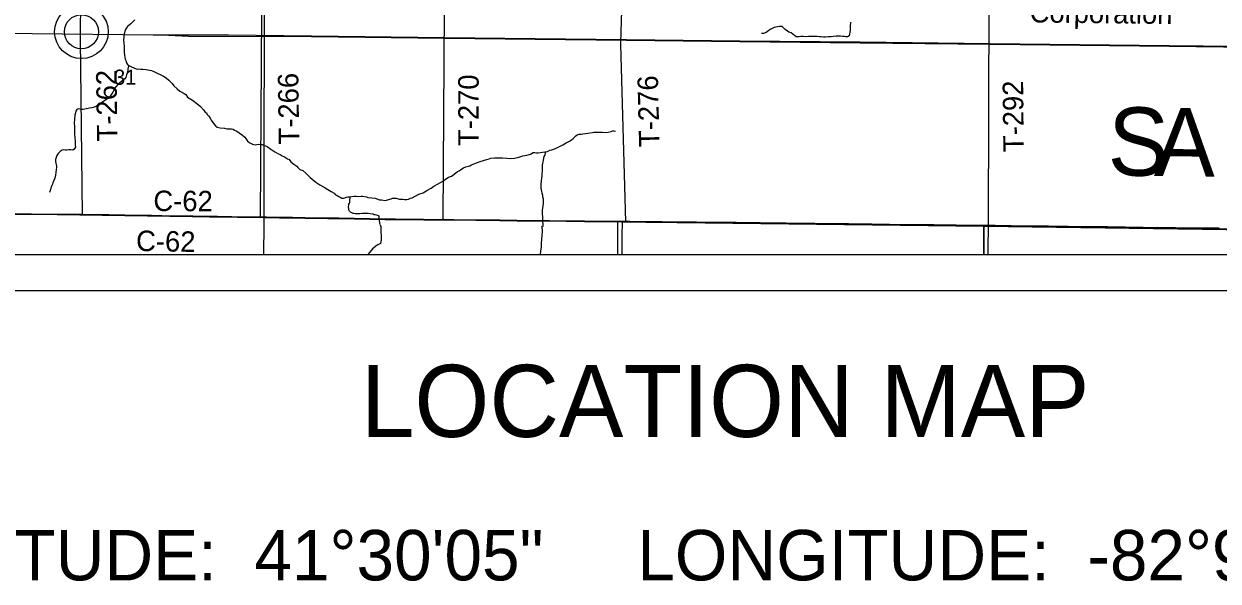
# Model space of a CAD drawing. Extents: x 0 to 34, y 0 to 22.
# Drawn here: x 3.493 to 6.805, y 13.194 to 14.74 of the extents above; entities that cross this region are included whole.
import ezdxf

# ---------------------------------------------------------------- set-up
doc = ezdxf.new("R2010")
doc.units = 0
for name, color, linetype in [('GM_X_County_Road', 7, 'Continuous'), ('GM_X_County_Road_Text', 7, 'Continuous'), ('GM_X_County_Text', 7, 'Continuous'), ('GM_X_Minor_River', 7, 'Continuous'), ('GM_X_Rail_Line', 7, 'Continuous'), ('GM_X_Rail_Line_Text', 7, 'Continuous'), ('GM_X_Section', 7, 'Continuous'), ('GM_X_Section_Text', 7, 'Continuous'), ('GM_X_Township_Road', 7, 'Continuous'), ('GM_X_Township_Road_Text', 7, 'Continuous'), ('GM_X_Unincorporated', 7, 'Continuous'), ('GM_X_Unincorporated_Location', 7, 'Continuous'), ('SH_Cut_Line', 7, 'Continuous'), ('SH_Data', 7, 'Continuous'), ('SH_Text', 7, 'Continuous')]:
    doc.layers.add(name, color=color, linetype=linetype)

msp = doc.modelspace()

# ---------------------------------------------------------------- linework, layer by layer
at = {"layer": 'GM_X_County_Road'}
msp.add_line((5.1526, 14.1908), (5.1623, 14.1907), dxfattribs=at)
for points in [[(3.1493, 14.2166), (3.1515, 14.2166), (3.2852, 14.2149), (3.3044, 14.2146), (3.3778, 14.2136), (3.4331, 14.2126), (3.4692, 14.2121), (3.5139, 14.2114), (3.586, 14.2106), (3.6556, 14.21)], [(3.6556, 14.21), (3.6718, 14.2099), (3.7284, 14.2091), (3.7731, 14.2086), (3.8465, 14.2072), (3.9043, 14.2062), (3.944, 14.206), (3.9621, 14.2057), (4.0074, 14.2048), (4.0298, 14.2045), (4.0696, 14.2041), (4.1317, 14.2031), (4.1559, 14.2029), (4.1594, 14.2029)], [(4.1594, 14.2029), (4.1659, 14.2028), (4.2013, 14.202), (4.2374, 14.2016), (4.2722, 14.2011), (4.3101, 14.2005), (4.3356, 14.2002), (4.3667, 14.1998), (4.4947, 14.1973), (4.5233, 14.1971), (4.5599, 14.1967), (4.6015, 14.1964), (4.6438, 14.1959), (4.655, 14.1959)], [(4.655, 14.1959), (4.6854, 14.1957), (4.7463, 14.1947), (4.8128, 14.1943), (4.86, 14.1937), (4.9502, 14.1929), (4.9968, 14.1921), (5.0478, 14.1916), (5.1273, 14.191), (5.1526, 14.1908)], [(5.1623, 14.1907), (5.1733, 14.1906), (5.2175, 14.19), (5.2629, 14.1896), (5.3169, 14.189), (5.3586, 14.1886), (5.4139, 14.1884), (5.468, 14.1877), (5.5351, 14.187), (5.5798, 14.1865), (5.6066, 14.1863), (5.6861, 14.1852), (5.7794, 14.1841), (5.8446, 14.1835), (5.8938, 14.1827), (5.9329, 14.182), (5.9596, 14.1818), (5.9895, 14.1814), (6.0162, 14.1812), (6.0435, 14.1807), (6.0784, 14.1803), (6.1169, 14.1801), (6.1474, 14.1798), (6.1678, 14.1796)], [(6.1678, 14.1796), (6.1865, 14.1794), (6.2754, 14.1783), (6.3065, 14.1782), (6.3345, 14.1776), (6.4439, 14.1764), (6.4992, 14.1756), (6.5968, 14.1744), (6.6366, 14.1738), (6.6608, 14.1736), (6.6869, 14.1732), (6.718, 14.1728), (6.8082, 14.1723), (6.8964, 14.1713), (6.9586, 14.1708), (7.0189, 14.1698), (7.1414, 14.1682), (7.177, 14.168)]]:
    msp.add_lwpolyline(points, dxfattribs=at)
at = {"layer": 'GM_X_Minor_River'}
for points in [[(3.8008, 14.7511), (3.7894, 14.7396), (3.7849, 14.7365), (3.7804, 14.7327), (3.7773, 14.7285), (3.7743, 14.7236), (3.7725, 14.719), (3.7717, 14.7144), (3.7702, 14.708), (3.7695, 14.7027), (3.7692, 14.6947), (3.7696, 14.6859), (3.7704, 14.6765), (3.7708, 14.6727), (3.7709, 14.6609), (3.7713, 14.6529), (3.7724, 14.6472), (3.774, 14.6419), (3.7755, 14.6377), (3.7775, 14.6317), (3.7801, 14.6271), (3.7855, 14.623), (3.7893, 14.6215), (3.7992, 14.6166), (3.8064, 14.6143), (3.8113, 14.6147), (3.8166, 14.614), (3.8223, 14.6144), (3.8318, 14.6129), (3.841, 14.6111), (3.8466, 14.6107), (3.8527, 14.6073), (3.8626, 14.6028), (3.8725, 14.5979), (3.8798, 14.5945), (3.8877, 14.5896), (3.895, 14.5836), (3.8996, 14.5791), (3.9038, 14.5745), (3.9087, 14.5681), (3.9175, 14.5594), (3.9255, 14.5534), (3.9373, 14.5466), (3.9419, 14.5436), (3.9465, 14.5364), (3.951, 14.5333), (3.9606, 14.5277), (3.9724, 14.5186), (3.9827, 14.5107), (3.9911, 14.5012), (3.9941, 14.4952), (3.9987, 14.4925), (4.001, 14.4884), (4.0048, 14.4846), (4.0071, 14.4808), (4.0098, 14.4766), (4.0125, 14.4729), (4.0163, 14.466), (4.0243, 14.457), (4.0289, 14.4532), (4.0372, 14.4513), (4.0486, 14.4499), (4.0555, 14.4484), (4.0638, 14.4488), (4.0684, 14.4484), (4.0726, 14.4477), (4.0767, 14.4451), (4.0832, 14.442), (4.0893, 14.4375), (4.0992, 14.4311), (4.1057, 14.4258), (4.1084, 14.4213), (4.1111, 14.4175), (4.1141, 14.4137), (4.1191, 14.4095), (4.1229, 14.4077), (4.1267, 14.4062), (4.1339, 14.4043), (4.143, 14.4062), (4.1487, 14.4051), (4.1532, 14.4048), (4.1593, 14.4025), (4.1631, 14.4014), (4.1673, 14.3991), (4.1772, 14.3924), (4.189, 14.3848), (4.1985, 14.3792), (4.2031, 14.3769), (4.2088, 14.3735), (4.2157, 14.3709), (4.2233, 14.3656), (4.2279, 14.363), (4.2332, 14.3569), (4.2412, 14.3505), (4.2492, 14.3452), (4.2523, 14.341), (4.2576, 14.3358), (4.2663, 14.3328), (4.2747, 14.3252)], [(5.7849, 14.7442), (5.7842, 14.7328), (5.7838, 14.7286), (5.7839, 14.7214), (5.7817, 14.7065), (5.7771, 14.7035), (5.7722, 14.7035), (5.768, 14.7042), (5.7631, 14.7049), (5.7578, 14.7053), (5.7536, 14.7057), (5.749, 14.7056), (5.7449, 14.7052), (5.7373, 14.7044), (5.7316, 14.7037), (5.7229, 14.7036), (5.716, 14.7032), (5.7103, 14.7032), (5.7035, 14.7035), (5.6989, 14.7035), (5.6925, 14.7042), (5.6864, 14.7042), (5.68, 14.7045), (5.6739, 14.7045), (5.6686, 14.7045), (5.6621, 14.7041), (5.6541, 14.7044), (5.6477, 14.7044)], [(5.6477, 14.7044), (5.6431, 14.704), (5.639, 14.7036), (5.6344, 14.704), (5.6207, 14.7145), (5.6142, 14.7168), (5.61, 14.719), (5.6036, 14.7243), (5.5997, 14.7289), (5.5952, 14.7319), (5.588, 14.7326), (5.5826, 14.7311), (5.5732, 14.7295), (5.5637, 14.7249), (5.5588, 14.7211), (5.5512, 14.7161), (5.5436, 14.7134), (5.5387, 14.7126)], [(3.7838, 14.6243), (3.7813, 14.6146), (3.7806, 14.6093), (3.7791, 14.6032), (3.7776, 14.5982), (3.775, 14.5906), (3.7727, 14.5868), (3.7644, 14.5811), (3.7584, 14.5761), (3.7535, 14.5719), (3.7444, 14.5605), (3.7422, 14.5559), (3.7395, 14.5502), (3.7361, 14.5445), (3.7316, 14.5387), (3.7271, 14.5342), (3.7218, 14.5303), (3.7169, 14.5273), (3.7116, 14.5235), (3.707, 14.52), (3.7014, 14.5151), (3.6972, 14.5128), (3.6927, 14.5105), (3.6847, 14.5074), (3.6809, 14.5066), (3.6748, 14.5054), (3.6711, 14.505), (3.6654, 14.5042), (3.6616, 14.5035), (3.6574, 14.5023), (3.6528, 14.5023), (3.6479, 14.5034), (3.6433, 14.5038), (3.6392, 14.5018), (3.6369, 14.4977), (3.6354, 14.4931), (3.6343, 14.4866), (3.6336, 14.4824), (3.6332, 14.4783), (3.6329, 14.4733), (3.6325, 14.4665), (3.6326, 14.4532), (3.633, 14.4467), (3.633, 14.4422), (3.6331, 14.4365), (3.6343, 14.4217), (3.6347, 14.4163), (3.6347, 14.4122), (3.6351, 14.4076), (3.6351, 14.4019), (3.6355, 14.3974), (3.6325, 14.3924), (3.6287, 14.3897), (3.6227, 14.3901), (3.6173, 14.3904), (3.6117, 14.3896), (3.6067, 14.3896), (3.6029, 14.39), (3.5984, 14.3896), (3.5931, 14.3854), (3.5878, 14.3804), (3.5836, 14.3743), (3.5818, 14.3694), (3.5803, 14.3637), (3.5799, 14.3576), (3.5811, 14.353), (3.5819, 14.3492), (3.5827, 14.3451), (3.5827, 14.3409), (3.5823, 14.3359), (3.5808, 14.3272), (3.5801, 14.3196), (3.5783, 14.3116), (3.5756, 14.3048), (3.5734, 14.2991), (3.5719, 14.2949), (3.5704, 14.2911), (3.5678, 14.2842), (3.5663, 14.2804), (3.564, 14.272)], [(5.0379, 14.4341), (5.0428, 14.4348), (5.0573, 14.4368), (5.0694, 14.4384), (5.0732, 14.4392), (5.085, 14.4396), (5.0975, 14.4389), (5.1051, 14.4386), (5.1134, 14.439), (5.121, 14.4413), (5.1256, 14.4428), (5.1294, 14.4425), (5.1335, 14.4417)], [(4.2747, 14.3252), (4.2866, 14.3135), (4.2923, 14.3086), (4.3022, 14.3006), (4.3136, 14.2931), (4.325, 14.2867), (4.3353, 14.2803), (4.3452, 14.275), (4.3532, 14.2701), (4.3563, 14.2663), (4.3616, 14.2637), (4.3658, 14.2607), (4.37, 14.2592), (4.3742, 14.2565), (4.3798, 14.2566), (4.387, 14.2585), (4.3912, 14.2597), (4.395, 14.2597), (4.4087, 14.262), (4.4151, 14.2617), (4.4216, 14.2609), (4.428, 14.2614), (4.4326, 14.2614), (4.4425, 14.2603), (4.4463, 14.2584), (4.4573, 14.2569), (4.4672, 14.2558), (4.4786, 14.2517), (4.4846, 14.2517), (4.4949, 14.2499), (4.5108, 14.2545), (4.5146, 14.2565), (4.5249, 14.2561), (4.5309, 14.2546), (4.5347, 14.2535), (4.5393, 14.2531), (4.5438, 14.2532), (4.548, 14.2524), (4.5549, 14.2521), (4.559, 14.2536), (4.5651, 14.2563), (4.5693, 14.2575), (4.5882, 14.2671), (4.5996, 14.2713), (4.6105, 14.2774), (4.6226, 14.2836), (4.6298, 14.2893), (4.6397, 14.2954), (4.6484, 14.2996), (4.6544, 14.3031), (4.6612, 14.3081), (4.6703, 14.3142), (4.6783, 14.3176), (4.6824, 14.3203), (4.6908, 14.3264), (4.6953, 14.3299), (4.6995, 14.3318), (4.704, 14.3356), (4.7119, 14.3406), (4.718, 14.3429), (4.7218, 14.3444), (4.729, 14.346), (4.7339, 14.3483), (4.7434, 14.3525), (4.7578, 14.3575), (4.7673, 14.3606), (4.7726, 14.3629), (4.7767, 14.3637), (4.7832, 14.3652), (4.7873, 14.3675), (4.798, 14.368), (4.8021, 14.3676), (4.82, 14.3677), (4.8321, 14.367), (4.8416, 14.3659), (4.853, 14.3667), (4.8655, 14.3698), (4.8761, 14.3733), (4.8875, 14.3752), (4.8974, 14.3783), (4.9049, 14.3825), (4.9095, 14.3826), (4.9144, 14.3822), (4.919, 14.3818), (4.9376, 14.3846), (4.9448, 14.3858), (4.9516, 14.3892), (4.9569, 14.39), (4.9622, 14.3923), (4.969, 14.395), (4.9762, 14.3984), (4.9876, 14.4038), (4.9967, 14.4092), (5.0057, 14.4142), (5.0114, 14.418), (5.0156, 14.4218), (5.0197, 14.4252), (5.0235, 14.4294), (5.0273, 14.4314), (5.0322, 14.4333), (5.0379, 14.4341)], [(4.9385, 14.3847), (4.9384, 14.3804), (4.9372, 14.3766), (4.935, 14.3713), (4.9328, 14.3618), (4.9316, 14.3564), (4.9313, 14.3519), (4.9302, 14.3477), (4.9302, 14.3352), (4.9299, 14.3295), (4.9291, 14.3257), (4.9288, 14.3192), (4.9281, 14.3108), (4.9273, 14.3048), (4.9266, 14.2953), (4.9263, 14.2911), (4.9263, 14.2842), (4.9271, 14.2797), (4.9286, 14.2748), (4.9294, 14.2706), (4.9306, 14.2645), (4.9306, 14.2607), (4.9325, 14.2546), (4.933, 14.2467), (4.9326, 14.241), (4.9315, 14.2345), (4.9311, 14.2284), (4.93, 14.2231), (4.9297, 14.2189), (4.9316, 14.178)], [(4.4807, 14.1828), (4.4781, 14.1988), (4.4777, 14.2019), (4.4777, 14.2045), (4.4774, 14.2076), (4.4747, 14.2084), (4.4702, 14.2092), (4.4672, 14.21), (4.4638, 14.2104), (4.4611, 14.2115), (4.4528, 14.2124), (4.4471, 14.2136), (4.4372, 14.2136), (4.4308, 14.2137), (4.4243, 14.2126), (4.4217, 14.2126), (4.4149, 14.2131), (4.4115, 14.2131), (4.408, 14.2135), (4.4054, 14.2139), (4.4024, 14.2151), (4.3986, 14.217), (4.3956, 14.2197), (4.3937, 14.2235), (4.3934, 14.2269), (4.3927, 14.233), (4.3934, 14.2364), (4.3942, 14.2391), (4.3954, 14.2421), (4.3962, 14.2455), (4.3966, 14.2482), (4.3976, 14.2603)], [(4.4805, 14.1826), (4.4824, 14.1775), (4.4824, 14.1638), (4.4835, 14.1501), (4.4839, 14.1406), (4.4819, 14.1304), (4.4721, 14.1258), (4.4599, 14.116), (4.4512, 14.105), (4.4469, 14.1)], [(4.9281, 14.1781), (4.9289, 14.1773), (4.9296, 14.1636), (4.9288, 14.1526), (4.9284, 14.1424), (4.9276, 14.1306), (4.9268, 14.1207), (4.9253, 14.1097), (4.9247, 14.1)]]:
    msp.add_lwpolyline(points, dxfattribs=at)
at = {"layer": 'GM_X_Rail_Line'}
for points in [[(2.1, 14.729), (2.1509, 14.7286), (2.6493, 14.723), (2.8845, 14.7204), (3.0329, 14.7186), (3.1572, 14.7171), (3.5158, 14.7132), (3.8511, 14.7095), (3.8755, 14.7092)], [(3.8755, 14.7092), (3.9489, 14.7058), (4.2907, 14.7042), (4.6589, 14.6997), (4.9948, 14.696), (5.1637, 14.6942), (5.4781, 14.6905), (5.8118, 14.687), (6.1724, 14.6829), (6.6691, 14.6774), (7.0452, 14.6733), (7.1775, 14.6715), (7.5411, 14.668), (8.0931, 14.662), (8.3488, 14.6591), (8.6241, 14.6565), (8.751, 14.655), (8.8576, 14.6516), (8.8713, 14.6516), (8.8802, 14.6518), (8.8941, 14.6527), (8.9, 14.6532)], [(3.8755, 14.7092), (4.0605, 14.7092), (4.2907, 14.7067), (4.659, 14.7022), (4.9948, 14.6985), (5.1637, 14.6967), (5.4782, 14.693), (5.8118, 14.6895), (6.1725, 14.6854), (6.6691, 14.6799), (7.0452, 14.6758), (7.1775, 14.6739), (7.5411, 14.6704), (8.0932, 14.6645), (8.3489, 14.6616), (8.6241, 14.659), (8.7511, 14.6575), (8.8576, 14.6541), (8.8712, 14.6541), (8.8801, 14.6543), (8.894, 14.6552), (8.9, 14.6557)]]:
    msp.add_lwpolyline(points, dxfattribs=at)
at = {"layer": 'GM_X_Section'}
msp.add_lwpolyline([(3.1571, 15.217), (4.1541, 15.2001), (4.1481, 14.2013), (3.1458, 14.2165)], close=True, dxfattribs=at)
at = {"layer": 'GM_X_Township_Road'}
for p, q in [((6.1678, 14.1796), (6.1703, 15.1871)), ((3.6496, 14.6996), (3.6526, 15.0232))]:
    msp.add_line(p, q, dxfattribs=at)
for points in [[(5.1485, 14.688), (5.1676, 15.3066), (5.1671, 15.5037), (5.1673, 15.6155), (5.165, 15.7242)], [(4.655, 14.1959), (4.6642, 15.507), (4.6673, 15.5158)], [(4.1594, 14.2029), (4.1598, 14.9242), (4.1615, 15.0983), (4.1626, 15.2315), (4.1623, 15.2495), (4.1604, 15.2545), (4.1568, 15.2599)], [(3.6556, 14.21), (3.6495, 14.6966), (3.6496, 14.6996)], [(5.1623, 14.1907), (5.1483, 14.6821), (5.1485, 14.688)], [(6.8079, 14.1728), (6.7178, 14.1734), (6.6867, 14.1738), (6.6606, 14.1741), (6.6364, 14.1743), (6.5966, 14.1749), (6.499, 14.1762), (6.4437, 14.177), (6.3342, 14.1781), (6.3063, 14.1787), (6.2752, 14.1788), (6.1863, 14.18), (6.1676, 14.1801), (6.1471, 14.1803), (6.1167, 14.1806), (6.0781, 14.1809), (6.0433, 14.1813), (6.016, 14.1818), (5.9893, 14.182), (5.9594, 14.1824), (5.9327, 14.1825), (5.8935, 14.1833), (5.8444, 14.184), (5.7792, 14.1847), (5.6859, 14.1858), (5.6063, 14.1868), (5.5796, 14.187), (5.5349, 14.1876), (5.4677, 14.1883), (5.4137, 14.1889), (5.3584, 14.1892), (5.3167, 14.1896), (5.2626, 14.1902), (5.2172, 14.1906), (5.1731, 14.1912), (5.1621, 14.1913), (5.1524, 14.1913), (5.1271, 14.1915), (5.0476, 14.1921), (4.9966, 14.1927), (4.95, 14.1934), (4.8598, 14.1942), (4.8126, 14.1948), (4.7461, 14.1953), (4.6852, 14.1962), (4.6547, 14.1964), (4.6436, 14.1965), (4.6013, 14.1969), (4.5597, 14.1972), (4.5231, 14.1977), (4.4945, 14.1979), (4.3664, 14.2004), (4.3354, 14.2007), (4.3099, 14.2011), (4.272, 14.2017), (4.2372, 14.2021), (4.2011, 14.2025), (4.1657, 14.2034), (4.1592, 14.2034), (4.1557, 14.2035), (4.1315, 14.2037), (4.0694, 14.2046), (4.0296, 14.2051), (4.0072, 14.2053), (3.9618, 14.2063), (3.9438, 14.2065), (3.904, 14.2067), (3.8462, 14.2077), (3.7729, 14.2092), (3.7281, 14.2096), (3.6716, 14.2104), (3.6553, 14.2105), (3.5858, 14.2111), (3.5137, 14.212), (3.4689, 14.2127)], [(3.4689, 14.2127), (3.5137, 14.212), (3.5858, 14.2111), (3.6553, 14.2105), (3.6716, 14.2104), (3.7281, 14.2096), (3.7729, 14.2092), (3.8462, 14.2077), (3.904, 14.2067), (3.9438, 14.2065), (3.9618, 14.2063), (4.0072, 14.2053), (4.0296, 14.2051), (4.0694, 14.2046), (4.1315, 14.2037), (4.1557, 14.2035), (4.1592, 14.2034), (4.1657, 14.2034), (4.2011, 14.2025), (4.2372, 14.2021), (4.272, 14.2017), (4.3099, 14.2011), (4.3354, 14.2007), (4.3664, 14.2004), (4.4945, 14.1979), (4.5231, 14.1977), (4.5597, 14.1972), (4.6013, 14.1969), (4.6436, 14.1965), (4.6547, 14.1964), (4.6852, 14.1962), (4.7461, 14.1953), (4.8126, 14.1948), (4.8598, 14.1942), (4.95, 14.1934), (4.9966, 14.1927), (5.0476, 14.1921), (5.1271, 14.1915), (5.1524, 14.1913), (5.1621, 14.1913), (5.1731, 14.1912), (5.2172, 14.1906), (5.2626, 14.1902), (5.3167, 14.1896), (5.3584, 14.1892), (5.4137, 14.1889), (5.4677, 14.1883), (5.5349, 14.1876), (5.5796, 14.187), (5.6063, 14.1868), (5.6859, 14.1858), (5.7792, 14.1847), (5.8444, 14.184), (5.8935, 14.1833), (5.9327, 14.1825), (5.9594, 14.1824), (5.9893, 14.182), (6.016, 14.1818), (6.0433, 14.1813), (6.0781, 14.1809), (6.1167, 14.1806), (6.1471, 14.1803), (6.1676, 14.1801), (6.1863, 14.18), (6.2752, 14.1788), (6.3063, 14.1787), (6.3342, 14.1781), (6.4437, 14.177), (6.499, 14.1762), (6.5966, 14.1749), (6.6364, 14.1743), (6.6606, 14.1741), (6.6867, 14.1738), (6.7178, 14.1734), (6.8079, 14.1728)], [(4.158, 14.1), (4.1594, 14.182), (4.1594, 14.197), (4.1594, 14.2029)], [(5.1519, 14.1), (5.1519, 14.1033), (5.1523, 14.1579), (5.1527, 14.184), (5.1527, 14.1874), (5.1526, 14.1908)], [(6.1666, 14.1), (6.1673, 14.1377), (6.1675, 14.157), (6.1678, 14.1757), (6.1678, 14.1796)], [(3.1468, 14.1), (8.9, 14.1)]]:
    msp.add_lwpolyline(points, dxfattribs=at)
at = {"layer": 'GM_X_Unincorporated'}
for points in [[(5.1391, 14.1), (6.1545, 14.1), (6.1553, 14.178), (5.1502, 14.1899), (5.1388, 14.1901)], [(6.1545, 14.1), (7.1637, 14.1), (7.1637, 14.1636), (6.1553, 14.178)]]:
    msp.add_lwpolyline(points, close=True, dxfattribs=at)
for radius in [0.0744, 0.0472]:
    msp.add_circle((3.6522, 14.7178), radius, dxfattribs=at)
at = {"layer": 'GM_X_Unincorporated_Location'}
msp.add_line((3.6522, 14.7178), (3.6522, 14.7178), dxfattribs=at)
at = {"layer": 'SH_Cut_Line'}
for points in [[(6.8079, 14.1728), (6.7178, 14.1734), (6.6867, 14.1738), (6.6606, 14.1741), (6.6364, 14.1743), (6.5966, 14.1749), (6.499, 14.1762), (6.4437, 14.177), (6.3342, 14.1781), (6.3063, 14.1787), (6.2752, 14.1788), (6.1863, 14.18), (6.1676, 14.1801), (6.1471, 14.1803), (6.1167, 14.1806), (6.0781, 14.1809), (6.0433, 14.1813), (6.016, 14.1818), (5.9893, 14.182), (5.9594, 14.1824), (5.9327, 14.1825), (5.8935, 14.1833), (5.8444, 14.184), (5.7792, 14.1847), (5.6859, 14.1858), (5.6063, 14.1868), (5.5796, 14.187), (5.5349, 14.1876), (5.4677, 14.1883), (5.4137, 14.1889), (5.3584, 14.1892), (5.3167, 14.1896), (5.2626, 14.1902), (5.2172, 14.1906), (5.1731, 14.1912), (5.1621, 14.1913), (5.1524, 14.1913), (5.1271, 14.1915), (5.0476, 14.1921), (4.9966, 14.1927), (4.95, 14.1934), (4.8598, 14.1942), (4.8126, 14.1948), (4.7461, 14.1953), (4.6852, 14.1962), (4.6547, 14.1964), (4.6436, 14.1965), (4.6013, 14.1969), (4.5597, 14.1972), (4.5231, 14.1977), (4.4945, 14.1979), (4.3664, 14.2004), (4.3354, 14.2007), (4.3099, 14.2011), (4.272, 14.2017), (4.2372, 14.2021), (4.2011, 14.2025), (4.1657, 14.2034), (4.1592, 14.2034), (4.1557, 14.2035), (4.1315, 14.2037), (4.0694, 14.2046), (4.0296, 14.2051), (4.0072, 14.2053), (3.9618, 14.2063), (3.9438, 14.2065), (3.904, 14.2067), (3.8462, 14.2077), (3.7729, 14.2092), (3.7281, 14.2096), (3.6716, 14.2104), (3.6553, 14.2105), (3.5858, 14.2111), (3.5137, 14.212), (3.4689, 14.2127)], [(3.4689, 14.2127), (3.5137, 14.212), (3.5858, 14.2111), (3.6553, 14.2105), (3.6716, 14.2104), (3.7281, 14.2096), (3.7729, 14.2092), (3.8462, 14.2077), (3.904, 14.2067), (3.9438, 14.2065), (3.9618, 14.2063), (4.0072, 14.2053), (4.0296, 14.2051), (4.0694, 14.2046), (4.1315, 14.2037), (4.1557, 14.2035), (4.1592, 14.2034), (4.1657, 14.2034), (4.2011, 14.2025), (4.2372, 14.2021), (4.272, 14.2017), (4.3099, 14.2011), (4.3354, 14.2007), (4.3664, 14.2004), (4.4945, 14.1979), (4.5231, 14.1977), (4.5597, 14.1972), (4.6013, 14.1969), (4.6436, 14.1965), (4.6547, 14.1964), (4.6852, 14.1962), (4.7461, 14.1953), (4.8126, 14.1948), (4.8598, 14.1942), (4.95, 14.1934), (4.9966, 14.1927), (5.0476, 14.1921), (5.1271, 14.1915), (5.1524, 14.1913), (5.1621, 14.1913), (5.1731, 14.1912), (5.2172, 14.1906), (5.2626, 14.1902), (5.3167, 14.1896), (5.3584, 14.1892), (5.4137, 14.1889), (5.4677, 14.1883), (5.5349, 14.1876), (5.5796, 14.187), (5.6063, 14.1868), (5.6859, 14.1858), (5.7792, 14.1847), (5.8444, 14.184), (5.8935, 14.1833), (5.9327, 14.1825), (5.9594, 14.1824), (5.9893, 14.182), (6.016, 14.1818), (6.0433, 14.1813), (6.0781, 14.1809), (6.1167, 14.1806), (6.1471, 14.1803), (6.1676, 14.1801), (6.1863, 14.18), (6.2752, 14.1788), (6.3063, 14.1787), (6.3342, 14.1781), (6.4437, 14.177), (6.499, 14.1762), (6.5966, 14.1749), (6.6364, 14.1743), (6.6606, 14.1741), (6.6867, 14.1738), (6.7178, 14.1734), (6.8079, 14.1728)], [(2.1, 14.1), (8.9, 14.1)]]:
    msp.add_lwpolyline(points, dxfattribs=at)
at = {"layer": 'SH_Data'}
for p, q in [((2.1, 14.1), (8.9, 14.1)), ((2, 14), (9, 14))]:
    msp.add_line(p, q, dxfattribs=at)

# ---------------------------------------------------------------- texts
at = {"layer": 'GM_X_County_Road_Text'}
for rotation, p in [(359.6636, (3.8517, 14.2205)), (358.9692, (3.8034, 14.1098))]:
    msp.add_text('C-62', height=0.05682, rotation=rotation, dxfattribs=at).set_placement(p)
at = {"layer": 'GM_X_County_Text'}
for s, rotation, p in [('S', 359.2121, (6.4977, 14.3196)), ('A', 359.2123, (6.6264, 14.3178))]:
    msp.add_text(s, height=0.1894, rotation=rotation, dxfattribs=at).set_placement(p)
at = {"layer": 'GM_X_Rail_Line_Text'}
msp.add_text('Corporation', height=0.056629, rotation=359.3598, dxfattribs=at).set_placement((6.2819, 14.7437))
at = {"layer": 'GM_X_Section_Text'}
msp.add_text('31', height=0.04186, rotation=0, dxfattribs=at).set_placement((3.7425, 14.5708))
at = {"layer": 'GM_X_Township_Road_Text'}
for s, rotation, p in [('T-262', 90.8421, (3.7524, 14.4139)), ('T-266', 90.8421, (4.2565, 14.4056)), ('T-270', 90, (4.754, 14.4008)), ('T-276', 91.4043, (5.2557, 14.399)), ('T-292', 90.5625, (6.2657, 14.3842))]:
    msp.add_text(s, height=0.05682, rotation=rotation, dxfattribs=at).set_placement(p)
at = {"layer": 'SH_Text'}
for s, height, p in [('LOCATION MAP', 0.2, (4.4269, 13.5938)), ('LATITUDE:  41°30\'05"     LONGITUDE:  -82°94\'10"', 0.14, (3.071, 13.1959))]:
    msp.add_text(s, height=height, dxfattribs=at).set_placement(p)

doc.saveas('drawing.dxf')
